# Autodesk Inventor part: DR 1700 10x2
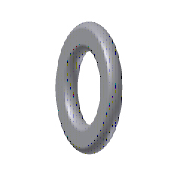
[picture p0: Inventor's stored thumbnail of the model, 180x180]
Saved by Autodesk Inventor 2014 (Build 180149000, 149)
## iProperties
IsCustomPart: 1
Created: 2009-11
Part Number: DR 1700 10x2
Material: ABS-DFA-R
Description: O Ring
Document SubType Name: Modeling
Designer: gaom
Standard Revision: 1
Manufacturer: DME
Language: en-US
Size Designation: 10x2
Categories: <MemberInstance><Categories><Category DisplayName="Mold" InternalName="349578f2-f4d4-4954-8c09-8e99297a61c0" Mnemonic="MOLD"><Category DisplayName="Cooling Comp
Density: 1.04 g/cm^3
Appearance: Default
Author: gaom
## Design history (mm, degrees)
sketch "Sketch1"
  geometry: L1 (0, -1.4)-(0, 1.4) reference; L2 (-1, 0)-(6, 0) reference; L3 (6.6, -0.8)-(5.4, -0.8); L4 (5.4, 0.8)-(6.6, 0.8); A1 r 1 centre (6, 0) between (5.4, 0.8) and (5.4, -0.8); A2 r 1 centre (6, 0) between (6.6, 0.8) and (5.4, 0.8); A3 r 1 centre (6, 0) between (6.6, -0.8) and (6.6, 0.8); A4 r 1 centre (6, 0) between (5.4, -0.8) and (6.6, -0.8); 1 further point
  constraints: 8 point on circle, 4 centre point, 4 end point, 3 parallel, 1 point on line
  dimensions: "d3" = 12 diameter of A1.centre L1 (= dx + d2); "d9" = 2 diameter of A1 (= d2); "d20" = 1.6 distance between parallel lines of L3 L4 (= t_CS)
revolve "Revolution1" sketch "Sketch1" stored, may be unused: angle "d24" = 90 deg
fillet "Fillet2" dims "d23" = 0.3
body "Solid1"
fillet "Fillet1" dims "d19" = 0.3 (= r)
sketch "Sketch2"
  geometry: L1 (-6.645, 0)-(7.668, 0) reference; L2 (0, -1.128)-(0, 1.166) reference; L3 (-6.6, 0.8)-(6.6, 0.8) reference; L4 (-6.6, -0.8)-(6.6, -0.8) reference; L5 (4.377, 0.8)-(7.623, 0.8); L6 (7.424, 0.617)-(7.3, -0.8); L7 (4.7, -0.8)-(7.3, -0.8); L8 (4.576, 0.617)-(4.7, -0.8); L9 (4.7, -0.8)-(4.7, 0.8); L10 (7.3, -0.8)-(7.3, 0.8); A1 r 1 centre (6, 0) between (6.6, -0.8) and (6.6, 0.8) reference; A2 r 0.2 centre (7.623, 0.6) between (7.623, 0.8) and (7.424, 0.617); A3 r 0.2 centre (4.377, 0.6) between (4.576, 0.617) and (4.377, 0.8); 1 further point
  constraints: 12 end point, 5 point on line, 4 point on circle, 4 tangent, 2 centre point, 2 perpendicular, 1 midpoint, 1 parallel, 1 vertical alignment
  dimensions: "d13" = 0.2 radius of A2 (= d100); "d14" = 0.2 radius of A3 (= d13); "d15" = 5 deg angle of L8 L9 (= d101); "d16" = 5 deg angle of L6 L10 (= d15); "d17" = 2.6 distance of L7.start L6.end (= b_CS)
body "Srf1"
feature "RevolutionSrf1" dims angle "d18" = 90 deg
other parameters: "dx" = 10 [user parameter; used in 1 equation term], "d2" = 2 [user parameter; used in 2 equation terms], "b_CS" = 2.6 [user parameter; used in 1 equation term], "t_CS" = 1.6 [user parameter; used in 1 equation term], "d21" = 0, "d22" = 0, "r" = 0.3 [user parameter; used in 1 equation term], "d100" = 0.2 [user parameter; used in 1 equation term], "d101" = 5 deg [user parameter; used in 1 equation term]
